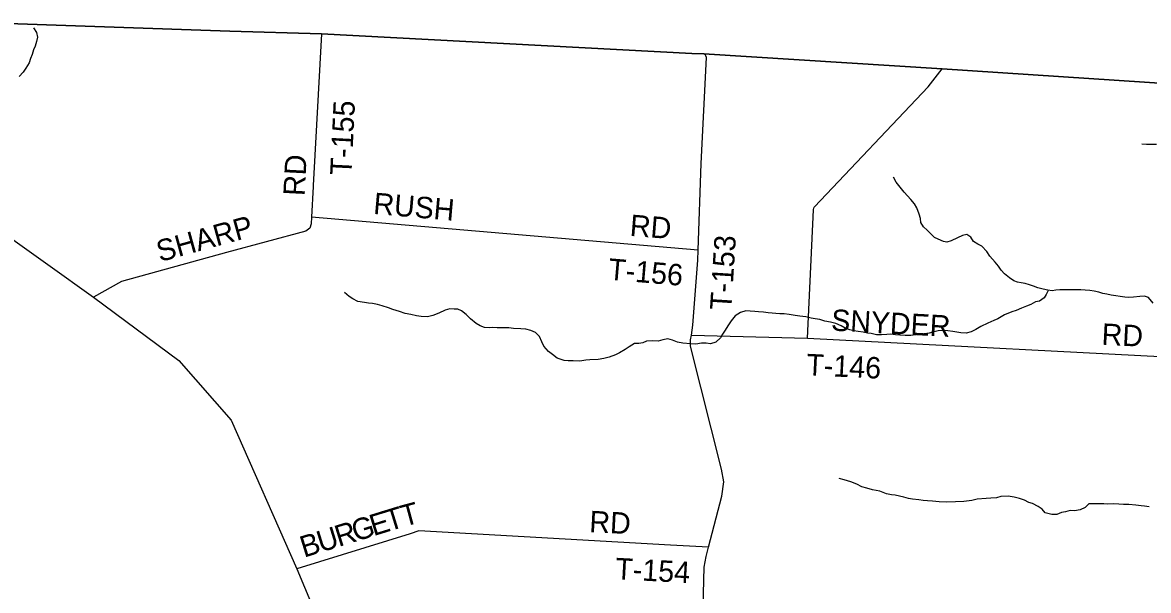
# Model space of a CAD drawing. Extents: x 1643459 to 2064572, y 425441 to 780708.
# Drawn here: x 1790021 to 1805814, y 651234 to 659196 of the extents above; entities that cross this region are included whole.
import ezdxf

# ---------------------------------------------------------------- set-up
doc = ezdxf.new("R2010")
doc.units = 0
for name, color, linetype in [('GM_X_City_Street', 7, 'Continuous'), ('GM_X_Interstate_Route', 7, 'Continuous'), ('GM_X_Major_River', 7, 'Continuous'), ('GM_X_Major_River_Text', 7, 'Continuous'), ('GM_X_US_Route', 7, 'Continuous'), ('RD_X_Text', 7, 'Continuous')]:
    doc.layers.add(name, color=color, linetype=linetype)

msp = doc.modelspace()

# ---------------------------------------------------------------- linework, layer by layer
at = {"layer": 'GM_X_City_Street'}
msp.add_lwpolyline([(1789408, 659196), (1792928, 659077), (1794213, 659039), (1799409, 658764), (1799575, 658756), (1802918, 658549), (1807036, 658278), (1811039, 658133), (1814713, 658027), (1815251, 658006), (1815551, 657995), (1819565, 657827), (1820365, 657774), (1824149, 657505)], dxfattribs=at)
at = {"layer": 'GM_X_Interstate_Route'}
msp.add_lwpolyline([(1824149, 657505), (1820365, 657774), (1819565, 657827), (1815551, 657995), (1815251, 658006), (1814713, 658027), (1811039, 658133), (1807036, 658278), (1802918, 658549), (1799575, 658756), (1799409, 658764), (1794213, 659039), (1792928, 659077), (1789408, 659196)], dxfattribs=at)
at = {"layer": 'GM_X_Major_River_Text'}
for points in [[(1794213, 659039), (1794100, 656910)], [(1799404, 654815), (1799424, 654955), (1799492, 655866), (1799496, 656004), (1799539, 657220), (1799613, 658707), (1799605, 658727)], [(1799605, 658727), (1799600, 658737), (1799575, 658756), (1799409, 658764)], [(1801128, 656612), (1802725, 658293), (1802918, 658549)], [(1794100, 656910), (1794099, 656897), (1794074, 656467), (1794068, 656372), (1794053, 656315), (1793993, 656273), (1792884, 655974), (1791409, 655566), (1791016, 655344)], [(1801030, 654769), (1801114, 656570), (1801122, 656599), (1801125, 656608), (1801128, 656612)], [(1799496, 656004), (1794074, 656467)], [(1799517, 648951), (1799582, 651562), (1799611, 651712), (1799644, 651840), (1799828, 652557), (1799859, 652759), (1799823, 652933), (1799388, 654661), (1799392, 654749), (1799404, 654815)], [(1799404, 654815), (1801030, 654769)], [(1801030, 654769), (1806788, 654474)], [(1799112, 651870), (1795580, 652068), (1795460, 652030), (1793870, 651535)], [(1799644, 651840), (1799112, 651870), (1799112, 651870)]]:
    msp.add_lwpolyline(points, dxfattribs=at)
at = {"layer": 'GM_X_US_Route'}
for points in [[(1790175, 659123), (1790215, 659055), (1790230, 658991), (1790216, 658931), (1790198, 658867), (1790176, 658813), (1790155, 658747), (1790135, 658691), (1790115, 658631), (1790066, 658555), (1790028, 658501), (1789972, 658439)], [(1805927, 657486), (1805787, 657488), (1805721, 657492)], [(1805879, 655261), (1805812, 655341), (1805758, 655358), (1805694, 655356), (1805603, 655345), (1805535, 655340), (1805483, 655344), (1805417, 655355), (1805356, 655365), (1805290, 655376), (1805228, 655387), (1805172, 655399), (1805116, 655414), (1805050, 655428), (1804990, 655439), (1804924, 655445), (1804866, 655448), (1804814, 655450), (1804750, 655449), (1804672, 655450), (1804572, 655451), (1804516, 655445), (1804462, 655436), (1804402, 655442), (1804336, 655457), (1804264, 655478), (1804200, 655500), (1804144, 655521), (1804082, 655539), (1804026, 655548), (1803976, 655556), (1803923, 655577), (1803865, 655615), (1803795, 655672), (1803748, 655726), (1803708, 655782), (1803663, 655835), (1803587, 655919), (1803546, 655985), (1803475, 656062), (1803421, 656088), (1803359, 656125), (1803320, 656187), (1803268, 656223), (1803206, 656212), (1803136, 656179), (1803047, 656134), (1802987, 656116), (1802937, 656127), (1802863, 656161), (1802813, 656184), (1802762, 656234), (1802710, 656284), (1802659, 656333), (1802623, 656395), (1802614, 656451), (1802596, 656511), (1802565, 656597), (1802530, 656655), (1802482, 656714), (1802436, 656766), (1802385, 656816), (1802276, 656959), (1802239, 657027)], [(1797676, 654454), (1797616, 654458), (1797520, 654491), (1797455, 654542), (1797399, 654584), (1797334, 654658), (1797304, 654721), (1797271, 654793), (1797218, 654849), (1797150, 654878), (1797080, 654898), (1797012, 654903), (1796908, 654908), (1796842, 654916), (1796758, 654917), (1796678, 654918), (1796620, 654919), (1796568, 654917), (1796500, 654922), (1796438, 654944), (1796382, 654977), (1796305, 655041), (1796243, 655102), (1796178, 655152), (1796128, 655177), (1796076, 655179), (1796016, 655182), (1795948, 655164), (1795859, 655121), (1795777, 655090), (1795701, 655071), (1795613, 655074), (1795547, 655086), (1795467, 655101), (1795387, 655118), (1795309, 655143), (1795217, 655173), (1795153, 655196), (1795064, 655225), (1795002, 655245), (1794932, 655256), (1794874, 655262), (1794820, 655269), (1794724, 655286), (1794656, 655322), (1794602, 655355), (1794537, 655409)], [(1804409, 655441), (1804379, 655385), (1804349, 655335), (1804286, 655292), (1804228, 655281), (1804162, 655243), (1804105, 655218), (1804033, 655193), (1803957, 655159), (1803895, 655140), (1803794, 655099), (1803703, 655042), (1803645, 655019), (1803559, 654980), (1803464, 654933), (1803390, 654894), (1803326, 654862), (1803255, 654841), (1803181, 654848), (1803125, 654856), (1803069, 654865), (1803001, 654873), (1802949, 654878), (1802865, 654873), (1802791, 654853), (1802739, 654842), (1802667, 654833), (1802607, 654823), (1802549, 654816), (1802481, 654809), (1802400, 654807), (1802328, 654812), (1802267, 654819), (1802199, 654825), (1802144, 654822), (1802068, 654819), (1801998, 654819), (1801926, 654836), (1801872, 654842), (1801813, 654853), (1801741, 654866), (1801683, 654876), (1801623, 654889), (1801559, 654911), (1801505, 654944), (1801427, 654978), (1801354, 654995), (1801276, 655010), (1801204, 655032), (1801140, 655041), (1801082, 655051), (1801010, 655068), (1800924, 655079), (1800860, 655091), (1800774, 655104), (1800702, 655111), (1800642, 655111), (1800588, 655116), (1800534, 655120), (1800480, 655125), (1800416, 655134), (1800346, 655140), (1800292, 655143), (1800228, 655151), (1800166, 655154), (1800090, 655131), (1800015, 655082), (1799959, 655014), (1799914, 654943), (1799876, 654883), (1799839, 654828), (1799809, 654776), (1799746, 654715), (1799672, 654692), (1799612, 654700), (1799546, 654701), (1799463, 654686), (1799390, 654693), (1799284, 654702), (1799208, 654716), (1799138, 654743), (1799072, 654761), (1799000, 654746), (1798936, 654731), (1798854, 654736), (1798775, 654730), (1798723, 654707), (1798667, 654694), (1798607, 654694), (1798531, 654649), (1798476, 654610), (1798396, 654564), (1798339, 654537), (1798251, 654504), (1798173, 654485), (1798095, 654470), (1797979, 654469), (1797924, 654463), (1797836, 654450), (1797746, 654455), (1797676, 654454)], [(1804134, 652469), (1804076, 652499), (1804003, 652522), (1803931, 652542), (1803845, 652555), (1803743, 652552), (1803682, 652531), (1803604, 652526), (1803538, 652524), (1803412, 652512), (1803338, 652494), (1803226, 652479), (1803108, 652476), (1802977, 652474), (1802879, 652475), (1802785, 652484), (1802713, 652490), (1802655, 652497), (1802595, 652503), (1802505, 652514), (1802448, 652523), (1802384, 652541), (1802322, 652556), (1802262, 652568), (1802210, 652573), (1802138, 652588), (1802046, 652626), (1801994, 652635), (1801944, 652647), (1801864, 652670), (1801793, 652685), (1801721, 652725), (1801639, 652756), (1801545, 652783), (1801477, 652803)], [(1805825, 652407), (1805759, 652417), (1805709, 652420), (1805637, 652430), (1805537, 652441), (1805463, 652440), (1805399, 652443), (1805323, 652447), (1805241, 652446), (1805187, 652449), (1805121, 652449), (1805033, 652450), (1804978, 652449), (1804928, 652395), (1804854, 652364), (1804775, 652349), (1804715, 652353), (1804649, 652336), (1804595, 652329), (1804527, 652299), (1804459, 652298), (1804363, 652321), (1804321, 652375), (1804268, 652410), (1804186, 652454), (1804134, 652469)]]:
    msp.add_lwpolyline(points, dxfattribs=at)
at = {"layer": 'RD_X_Text'}
msp.add_lwpolyline([(1784246, 657416), (1784376, 657379), (1784506, 657343), (1784874, 657325), (1785227, 657309), (1785368, 657303), (1785894, 657223), (1788277, 656990), (1788596, 656986), (1788740, 656956), (1789264, 656595), (1789821, 656200), (1790375, 655803), (1791016, 655344), (1792215, 654458), (1792947, 653623), (1793870, 651535), (1794301, 650507), (1795347, 649725), (1796257, 649043), (1799517, 648951), (1802807, 648835), (1805386, 648165), (1805438, 648152)], dxfattribs=at)

# ---------------------------------------------------------------- texts
at = {"layer": 'GM_X_Major_River'}
for s, rotation, p in [('T-155', 87.193, (1794634, 657049)), ('RD', 87.067, (1793978, 656760)), ('RUSH', 355.086, (1794934, 656514)), ('RD', 355.5256, (1798532, 656206)), ('SHARP', 15.478, (1791948, 655837)), ('T-153', 86.3615, (1799962, 655159)), ('T-156', 355.2135, (1798228, 655592)), ('SNYDER', 356.9057, (1801358, 654878)), ('RD', 357.0388, (1805151, 654680)), ('T-146', 357.1941, (1801010, 654253)), ('T', 17.1717, (1795158, 652060)), ('T', 15.1495, (1795370, 652126)), ('G', 17.2293, (1794692, 651916)), ('E', 17.2247, (1794944, 651994)), ('RD', 357.0131, (1797966, 652053)), ('U', 17.2293, (1794204, 651765)), ('R', 17.2241, (1794456, 651843)), ('B', 17.2241, (1793969, 651692)), ('T-154', 356.9051, (1798330, 651393))]:
    msp.add_text(s, height=300, rotation=rotation, dxfattribs=at).set_placement(p)

doc.saveas('drawing.dxf')
